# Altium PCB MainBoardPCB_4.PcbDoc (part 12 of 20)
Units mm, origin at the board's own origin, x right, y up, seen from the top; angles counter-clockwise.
Board outline 333.63 x 349.38 mm, 16 copper layers (L1, L2 (GND), L3 (Sign), L4 (GND), L5 (Sign), L6 (PWR/GND), L7(PWR/GND), L8 (Plane_GND), L9 (PWR/GND), L10 (PWR/GND), L11 (PWR/GND), L12 (Sign), L13 (GND), L14 (Sign), L15 (GND), L16), stack 2.502 mm thick; 2205 components, 1648 nets, 8314 pads, 3172 vias.
Unrouted connection lines stored in the file: 5141.
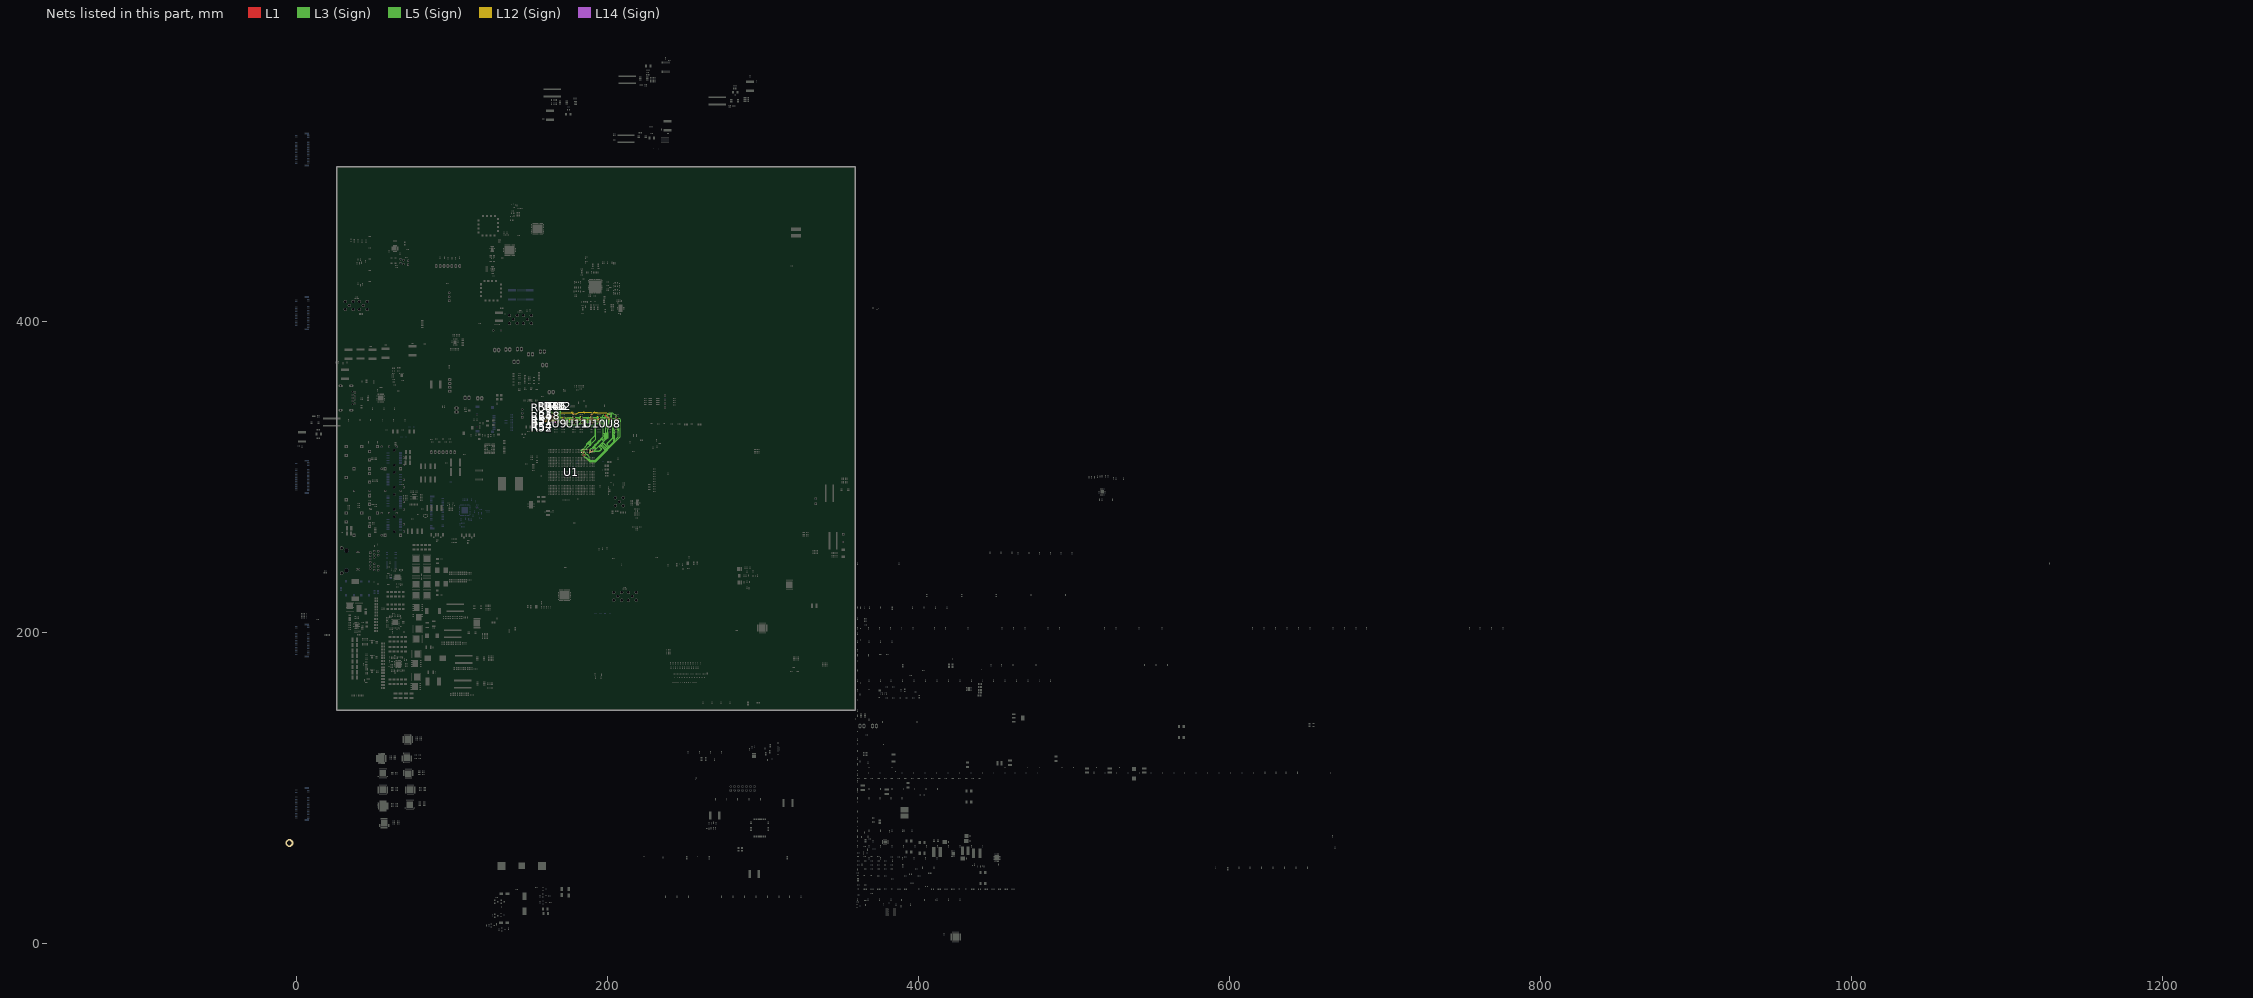
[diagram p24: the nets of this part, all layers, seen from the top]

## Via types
v1: diameter 0.5, hole 0.2, L1 to L16, tented both sides, 1153 vias
v2: diameter 0.5/0.35/0.35/0.35/0.35/0.35/0.35/0.35/0.35/0.35/0.35/0.35/0.35/0.35/0.35/0.5 (per signal layer), hole 0.2, L1 to L16, tented both sides, 548 vias
v3: diameter 0.5, hole 0.2, L1 to L16, 522 vias
v4: diameter 0.5/0.35/0.35/0.35/0.35/0.35/0.35/0.35/0.35/0.35/0.35/0.35/0.35/0.35/0.35/0.5 (per signal layer), hole 0.15, L1 to L16, tented both sides, 266 vias
v5: diameter 0.8, hole 0.4, L1 to L16, tented both sides, 164 vias
v6: diameter 0.35/0/0.35 (per signal layer), hole 0.127, L1 to L3 (Sign), tented both sides, 132 vias
v7: diameter 2.54, hole 1.02, L1 to L16, 125 vias
v8: diameter 1.4, hole 0.5, L1 to L16, tented both sides, 80 vias
v9: diameter 0.35, hole 0.127, L1 to L2 (GND), tented both sides, 36 vias
v10: diameter 0.4, hole 0.2, L1 to L16, 16 vias
v11: diameter 0.25, hole 0.2, L1 to L16, 16 vias
v12: diameter 5, hole 3, L1 to L16, 15 vias
v13: diameter 0.3, hole 0.2, L1 to L16, 15 vias
v14: diameter 0.45, hole 0.15, L1 to L16, 12 vias
v15: diameter 0.5/0.35/0.35/0.35/0.35/0.35/0.35/0.35/0.35/0.35/0.35/0.35/0.35/0.35/0.35/0.45 (per signal layer), hole 0.15, L1 to L16, tented both sides, 10 vias
v16: diameter 0.2/0/0.2 (per signal layer), hole 0.1, L1 to L3 (Sign), tented both sides, 9 vias
v17: diameter 0.4, hole 0.1, L1 to L16, 7 vias
v18: diameter 0.5, hole 0.2, L3 (Sign) to L6 (PWR/GND), tented both sides, 6 vias
v19: diameter 1.65, hole 1.65, L1 to L16, 6 vias
v20: diameter 1.15, hole 1.15, L1 to L16, 6 vias
v21: diameter 0.35/0/0.35 (per signal layer), hole 0.127, L14 (Sign) to L16, tented both sides, 5 vias
v22: diameter 0.2, hole 0.1, L1 to L16, 4 vias
v23: diameter 0.4, hole 0.2, L1 to L16, tented both sides, 2 vias
v24: diameter 0.4, hole 0.15, L1 to L16, 2 vias
v25: diameter 0.508, hole 0.127, L1 to L2 (GND), 2 vias
v26: diameter 0.508, hole 0.127, L2 (GND) to L3 (Sign), 2 vias
v27: diameter 0.5/0.35/0.35/0.35/0.35/0.35/0.35/0.35/0.35/0.35/0.35/0.35/0.35/0.35/0.35/0.5 (per signal layer), hole 0.15, L1 to L16, 2 vias
v28: diameter 0.35, hole 0.127, L3 (Sign) to L6 (PWR/GND), tented both sides, 2 vias
v29: diameter 5.5, hole 3.5, L1 to L16, 1 vias
v30: diameter 0.5/0.35/0.35/0.35/0.35/0.35/0.35/0.35/0.35/0.35/0.35/0.35/0.35/0.35/0.35/0.5 (per signal layer), hole 0.2, L1 to L16, 1 vias
v31: diameter 0.35/0.35/0.35 (per signal layer), hole 0.127, L1 to L3 (Sign), tented both sides, 1 vias
v32: diameter 0.45/0/0.45 (per signal layer), hole 0.15, L1 to L3 (Sign), tented both sides, 1 vias
v33: diameter 0.45/0/0.45 (per signal layer), hole 0.2, L14 (Sign) to L16, tented both sides, 1 vias
v34: diameter 0.35, hole 0.127, L2 (GND) to L3 (Sign), 1 vias
v35: diameter 0.35, hole 0.127, L1 to L2 (GND), 1 vias

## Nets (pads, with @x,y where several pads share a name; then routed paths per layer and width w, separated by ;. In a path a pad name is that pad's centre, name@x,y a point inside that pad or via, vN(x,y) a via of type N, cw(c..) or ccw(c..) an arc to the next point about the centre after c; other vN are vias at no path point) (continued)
DDR4_A12: R51.1 U1.AH29 U8.M4 U9.M4 U10.M4 U11.M4 | length 100.2
  L1 w0.116: U9.M4@167.676,336.86 168.072,337.257 v4(168.075,337.257) ; U11.M4@179.136,336.86 179.533,337.257 v4(179.535,337.257) ; U1.AH29@189.397,316.539 v6(189.884,317.027) ; U10.M4@190.597,336.86 190.993,337.257 v4(190.995,337.257) ; U8.M4@202.057,336.86 202.453,337.257 v4(202.456,337.257) v4@202.41,337.303
  L1 w0.155: R51.1@158.737,335.789 v1(159.982,335.789)
  L12 (Sign) w0.092: 165.251,336.237 165.445,336.237 165.539,336.143 165.892,336.143 166.604,336.855 167.465,336.855 167.867,337.257 v4(168.075,337.257) 168.075,337.251 168.611,336.715 173.117,336.715 173.251,336.715 ccw(c173.251,336.805) 173.34,336.805 173.34,336.915 cw(c173.43,336.915) 173.43,337.004 173.699,337.004 cw(c173.699,336.915) 173.788,336.915 173.788,336.805 ccw(c173.878,336.805) 173.878,336.715 174.146,336.715 ccw(c174.146,336.805) 174.236,336.805 174.236,336.915 cw(c174.326,336.915) 174.326,337.004 174.594,337.004 cw(c174.594,336.915) 174.684,336.915 174.684,336.805 ccw(c174.773,336.805) 174.773,336.715 175.743,336.715 177.622,336.715 177.768,336.86 179.109,336.86 179.505,337.257 v4(179.535,337.257) 180.267,337.257 180.961,336.563 184.861,336.563 185.159,336.86 186.83,336.86 187.355,336.86 ccw(c187.355,336.93) 187.425,336.93 187.425,337.109 cw(c187.494,337.109) 187.494,337.178 187.702,337.178 cw(c187.702,337.109) 187.771,337.109 187.771,336.86 187.771,336.612 ccw(c187.84,336.612) 187.84,336.543 188.048,336.543 ccw(c188.048,336.612) 188.117,336.612 188.117,336.791 cw(c188.186,336.791) 188.186,336.86 188.29,336.86 190.391,336.86 190.788,337.257 v4(190.995,337.257) 191.254,337.257 191.915,336.596 192.109,336.596 ccw(c192.109,336.626) 192.139,336.626 cw(c192.228,336.626) 192.228,336.715 192.497,336.715 cw(c192.497,336.626) 192.587,336.626 192.587,336.596 192.587,336.388 ccw(c192.676,336.388) 192.676,336.299 192.945,336.299 ccw(c192.945,336.388) 193.034,336.388 193.034,336.596 193.034,336.617 cw(c193.124,336.617) 193.124,336.707 193.393,336.707 cw(c193.393,336.617) 193.482,336.617 193.482,336.596 193.482,336.388 ccw(c193.572,336.388) 193.572,336.299 193.841,336.299 ccw(c193.841,336.388) 193.93,336.388 193.93,336.506 cw(c194.02,336.506) 194.02,336.596 194.288,336.596 cw(c194.288,336.506) 194.378,336.506 194.378,336.388 ccw(c194.467,336.388) 194.467,336.299 194.736,336.299 ccw(c194.736,336.388) 194.826,336.388 194.826,336.506 cw(c194.915,336.506) 194.915,336.596 195.123,336.596 201.075,336.596 201.394,336.915 201.768,336.915 202.155,337.303 202.41,337.303 v4(202.456,337.257)
  L12 (Sign) w0.151: v1(159.982,335.789) 163,335.789 163.448,336.237 165.251,336.237
  L3 (Sign) w0.092: v6(189.884,317.027) 190.205,316.706 191.727,316.706 199.386,324.364 199.765,324.364 200.51,325.11 200.51,328.276 200.406,328.38 200.406,330.432 200.406,331.001 cw(c200.505,331.001) 200.505,331.1 200.776,331.1 ccw(c200.776,331.199) 200.875,331.199 200.875,331.398 ccw(c200.776,331.398) 200.776,331.497 200.406,331.497 199.28,331.497 cw(c199.28,331.596) 199.181,331.596 199.181,331.795 cw(c199.28,331.795) 199.28,331.894 200.406,331.894 200.851,331.894 ccw(c200.851,331.993) 200.95,331.993 200.95,332.192 ccw(c200.851,332.192) 200.851,332.291 200.406,332.291 199.23,332.291 cw(c199.23,332.39) 199.13,332.39 199.13,332.589 cw(c199.23,332.589) 199.23,332.688 200.406,332.688 200.773,332.688 ccw(c200.773,332.787) 200.872,332.787 200.872,332.986 ccw(c200.773,332.986) 200.773,333.085 200.406,333.085 198.963,333.085 cw(c198.963,333.184) 198.864,333.184 198.864,333.383 cw(c198.963,333.383) 198.963,333.482 200.406,333.482 200.437,333.482 ccw(c200.437,333.581) 200.536,333.581 200.536,333.78 ccw(c200.437,333.78) 200.437,333.879 200.406,333.879 199.227,333.879 cw(c199.227,333.978) 199.128,333.978 199.128,334.177 cw(c199.227,334.177) 199.227,334.276 200.406,334.276 200.459,334.276 ccw(c200.459,334.375) 200.558,334.375 200.558,334.574 ccw(c200.459,334.574) 200.459,334.673 200.406,334.673 199.434,334.673 cw(c199.434,334.772) 199.334,334.772 199.334,334.971 cw(c199.434,334.971) 199.434,335.07 200.406,335.07 200.927,335.07 ccw(c200.927,335.169) 201.026,335.169 201.026,335.368 ccw(c200.927,335.368) 200.927,335.467 200.406,335.467 199.685,335.467 cw(c199.685,335.566) 199.586,335.566 199.586,335.765 cw(c199.685,335.765) 199.685,335.864 200.406,335.864 201.051,335.864 ccw(c201.051,335.963) 201.15,335.963 201.15,336.162 ccw(c201.051,336.162) 201.051,336.261 200.505,336.261 cw(c200.505,336.36) 200.406,336.36 200.406,336.459 200.807,336.86 202.059,336.86 v4(202.456,337.257)
DDR4_A13: R53.1 U1.AH28 U8.T5 U9.T5 U10.T5 U11.T5 | length 100.7
  L1 w0.116: U9.T5@166.876,340.06 167.274,340.459 v27(167.274,340.589) ; U11.T5@178.336,340.06 178.733,340.457 v4(178.735,340.457) ; v6(189.04,315.049) 189.04,315.182 U1.AH28@189.397,315.539 ; U10.T5@189.797,340.06 190.195,340.459 v4(190.195,340.589) ; U8.T5@201.257,340.06 201.653,340.457 v4(201.656,340.457)
  L1 w0.155: R53.1@158.737,344.5 v1(159.982,344.5)
  L12 (Sign) w0.092: 165.251,340.851 166.416,340.851 166.678,340.589 v27(167.274,340.589) 167.571,340.589 168.155,341.173 176.774,341.173 176.81,341.173 ccw(c176.81,341.262) 176.9,341.262 176.9,341.299 cw(c176.989,341.299) 176.989,341.389 177.258,341.389 cw(c177.258,341.299) 177.347,341.299 177.347,341.173 177.347,341.046 ccw(c177.437,341.046) 177.437,340.957 177.706,340.957 ccw(c177.706,341.046) 177.795,341.046 177.795,341.083 cw(c177.885,341.083) 177.885,341.173 178.019,341.173 v4(178.735,340.457) 180.475,340.457 181.559,341.541 184.15,341.541 184.793,341.541 ccw(c184.793,341.61) 184.862,341.61 184.862,341.755 cw(c184.931,341.755) 184.931,341.824 185.139,341.824 cw(c185.139,341.755) 185.208,341.755 185.208,341.541 185.208,341.327 ccw(c185.277,341.327) 185.277,341.258 185.485,341.258 ccw(c185.485,341.327) 185.554,341.327 185.554,341.472 cw(c185.624,341.472) 185.624,341.541 185.727,341.541 189.243,341.541 v4(190.195,340.589) 190.492,340.589 191.076,341.173 191.211,341.173 ccw(c191.211,341.262) 191.3,341.262 191.3,341.434 cw(c191.39,341.434) 191.39,341.523 191.658,341.523 cw(c191.658,341.434) 191.748,341.434 191.748,341.262 ccw(c191.838,341.262) 191.838,341.173 192.106,341.173 ccw(c192.106,341.262) 192.196,341.262 192.196,341.434 cw(c192.285,341.434) 192.285,341.523 192.554,341.523 cw(c192.554,341.434) 192.644,341.434 192.644,341.262 ccw(c192.733,341.262) 192.733,341.173 193.002,341.173 ccw(c193.002,341.262) 193.091,341.262 193.091,341.434 cw(c193.181,341.434) 193.181,341.523 193.45,341.523 cw(c193.45,341.434) 193.539,341.434 193.539,341.262 ccw(c193.629,341.262) 193.629,341.173 194.164,341.173 199.436,341.173 200.152,340.457 v4(201.656,340.457)
  L12 (Sign) w0.151: v1(159.982,344.5) 160.782,344.5 164.431,340.851 165.251,340.851
  L3 (Sign) w0.092: v6(189.04,315.049) 189.04,315.182 189.546,315.688 189.546,316.37 189.04,316.876 189.04,317.636 189.793,318.389 190.017,318.389 190.158,318.529 cw(c190.199,318.571) 190.158,318.612 190.355,318.81 cw(c190.397,318.769) 190.438,318.81 190.855,318.394 ccw(c190.925,318.464) 190.995,318.394 191.136,318.534 ccw(c191.065,318.604) 191.136,318.674 190.719,319.091 cw(c190.761,319.132) 190.719,319.174 190.917,319.372 cw(c190.958,319.33) 191,319.372 192.149,318.222 ccw(c192.22,318.292) 192.29,318.222 192.43,318.362 ccw(c192.36,318.433) 192.43,318.503 191.281,319.652 cw(c191.322,319.694) 191.281,319.735 191.478,319.933 cw(c191.52,319.891) 191.561,319.933 191.795,319.699 ccw(c191.866,319.769) 191.936,319.699 192.076,319.839 ccw(c192.006,319.909) 192.076,319.98 191.842,320.214 cw(c191.884,320.255) 191.842,320.297 192.04,320.494 cw(c192.081,320.453) 192.123,320.494 192.357,320.26 ccw(c192.427,320.33) 192.497,320.26 192.638,320.401 ccw(c192.567,320.471) 192.638,320.541 192.404,320.775 cw(c192.445,320.817) 192.404,320.858 192.601,321.056 cw(c192.643,321.014) 192.684,321.056 192.918,320.822 ccw(c192.989,320.892) 193.059,320.822 193.199,320.962 ccw(c193.129,321.032) 193.199,321.102 192.965,321.337 cw(c193.007,321.378) 192.965,321.42 193.163,321.617 cw(c193.204,321.576) 193.246,321.617 193.48,321.383 ccw(c193.55,321.453) 193.62,321.383 193.761,321.524 ccw(c193.69,321.594) 193.761,321.664 193.526,321.898 cw(c193.568,321.94) 193.526,321.981 193.724,322.179 cw(c193.766,322.137) 193.807,322.179 194.041,321.945 ccw(c194.111,322.015) 194.182,321.945 194.322,322.085 ccw(c194.252,322.155) 194.322,322.225 194.088,322.459 cw(c194.129,322.501) 194.088,322.543 194.285,322.74 cw(c194.327,322.699) 194.369,322.74 194.603,322.506 ccw(c194.673,322.576) 194.743,322.506 194.883,322.646 ccw(c194.813,322.717) 194.883,322.787 194.649,323.021 cw(c194.691,323.062) 194.649,323.104 194.847,323.302 cw(c194.888,323.26) 194.93,323.302 195.164,323.068 ccw(c195.234,323.138) 195.304,323.068 195.445,323.208 ccw(c195.375,323.278) 195.445,323.348 195.211,323.582 cw(c195.252,323.624) 195.211,323.665 195.408,323.863 cw(c195.45,323.821) 195.491,323.863 195.726,323.629 ccw(c195.796,323.699) 195.866,323.629 196.006,323.769 ccw(c195.936,323.84) 196.006,323.91 195.772,324.144 cw(c195.814,324.185) 195.772,324.227 195.97,324.424 cw(c196.011,324.383) 196.053,324.425 197.051,323.427 ccw(c197.121,323.497) 197.191,323.427 197.331,323.567 ccw(c197.261,323.637) 197.331,323.708 196.334,324.705 196.211,324.828 cw(c196.281,324.898) 196.211,324.968 196.351,325.109 cw(c196.421,325.039) 196.492,325.109 196.544,325.056 ccw(c196.614,325.126) 196.685,325.056 196.759,325.131 197.28,325.652 197.28,334.491 201.168,338.379 201.975,338.379 202.135,338.538 202.135,338.99 202.323,339.178 ; v4(201.656,340.457) 202.379,340.457 202.616,340.22 202.616,339.47 202.323,339.178
DDR4_ACT_N: R40.1 U1.AD26 U8.L3 U9.L3 U10.L3 U11.L3 | length 104
  L1 w0.116: v4(170.472,335.657) U9.L3@170.876,336.06 ; v4(181.933,335.657) U11.L3@182.336,336.06 ; U1.AD26@185.397,313.539 185.89,314.033 v6(186.017,314.033) ; v4(193.393,335.657) U10.L3@193.797,336.06 ; U8.L3@205.257,336.06 v15(205.661,335.657)
  L1 w0.155: v1(166.395,343.555) R40.1@166.395,344.799
  L5 (Sign) w0.092: 168.694,341.085 168.694,340.953 168.985,340.662 168.985,337.144 v4(170.472,335.657) 170.824,336.008 173.503,336.008 174.251,335.26 175.057,335.26 175.191,335.26 ccw(c175.191,335.35) 175.281,335.35 175.281,335.407 cw(c175.37,335.407) 175.37,335.497 175.639,335.497 cw(c175.639,335.407) 175.728,335.407 175.728,335.26 175.728,335.13 ccw(c175.818,335.13) 175.818,335.04 176.087,335.04 ccw(c176.087,335.13) 176.176,335.13 176.176,335.171 cw(c176.266,335.171) 176.266,335.26 176.657,335.26 180.028,335.26 180.425,335.657 v4(181.933,335.657) 182.336,336.06 184.472,336.06 185.265,335.267 185.356,335.267 185.46,335.267 ccw(c185.46,335.337) 185.53,335.337 185.53,335.406 cw(c185.599,335.406) 185.599,335.475 185.807,335.475 cw(c185.807,335.406) 185.876,335.406 185.876,335.267 185.876,335.129 ccw(c185.945,335.129) 185.945,335.059 186.153,335.059 ccw(c186.153,335.129) 186.222,335.129 186.222,335.267 186.222,335.406 cw(c186.291,335.406) 186.291,335.475 186.499,335.475 cw(c186.499,335.406) 186.568,335.406 186.568,335.337 ccw(c186.637,335.337) 186.637,335.267 186.715,335.267 191.656,335.267 192.045,335.657 v4(193.393,335.657) 193.816,336.08 195.631,336.08 195.885,335.826 197.417,335.826 198.076,335.826 cw(c198.076,335.737) 198.165,335.737 198.165,335.628 ccw(c198.255,335.628) 198.255,335.539 198.523,335.539 ccw(c198.523,335.628) 198.613,335.628 198.613,335.826 198.613,335.844 cw(c198.702,335.844) 198.702,335.933 198.971,335.933 cw(c198.971,335.844) 199.061,335.844 199.061,335.826 199.061,335.628 ccw(c199.15,335.628) 199.15,335.539 199.419,335.539 ccw(c199.419,335.628) 199.509,335.628 199.509,335.826 199.509,335.844 cw(c199.598,335.844) 199.598,335.933 199.867,335.933 cw(c199.867,335.844) 199.956,335.844 199.956,335.826 199.956,335.628 ccw(c200.046,335.628) 200.046,335.539 200.315,335.539 ccw(c200.315,335.628) 200.404,335.628 200.404,335.826 200.404,336.024 cw(c200.494,336.024) 200.494,336.113 200.762,336.113 cw(c200.762,336.024) 200.852,336.024 200.852,335.916 ccw(c200.941,335.916) 200.941,335.826 201.3,335.826 201.524,335.826 202.667,335.826 202.971,336.131 204.711,336.131 205.41,336.829 205.765,336.829 205.974,336.62 205.974,335.978 205.661,335.664 v15(205.661,335.657)
  L5 (Sign) w0.151: v1(166.395,343.555) 167.071,342.879 167.648,342.879 168.694,341.833 168.694,341.085
  L3 (Sign) w0.092: v6(186.017,314.033) 186.498,314.514 187.085,314.514 187.528,314.071 187.528,313.862 188.205,313.185 188.205,313.181 188.227,313.16 188.227,311.353 188.962,310.618 192.216,310.618 204.202,322.604 204.202,322.802 204.202,323.1 cw(c204.301,323.1) 204.301,323.199 204.674,323.199 ccw(c204.674,323.299) 204.774,323.299 204.774,323.497 ccw(c204.674,323.497) 204.674,323.596 204.301,323.596 cw(c204.301,323.696) 204.202,323.696 204.202,323.894 cw(c204.301,323.894) 204.301,323.993 204.674,323.993 ccw(c204.674,324.093) 204.774,324.093 204.774,324.291 ccw(c204.674,324.291) 204.674,324.39 204.301,324.39 cw(c204.301,324.49) 204.202,324.49 204.202,324.688 cw(c204.301,324.688) 204.301,324.787 204.6,324.787 ccw(c204.6,324.887) 204.699,324.887 204.699,325.085 ccw(c204.6,325.085) 204.6,325.184 204.301,325.184 cw(c204.301,325.284) 204.202,325.284 204.202,325.482 cw(c204.301,325.482) 204.301,325.581 204.6,325.581 ccw(c204.6,325.681) 204.699,325.681 204.699,325.879 ccw(c204.6,325.879) 204.6,325.978 204.301,325.978 cw(c204.301,326.078) 204.202,326.078 204.202,326.276 cw(c204.301,326.276) 204.301,326.375 204.674,326.375 ; 204.674,326.375 ccw(c204.674,326.475) 204.774,326.475 204.774,326.673 ccw(c204.674,326.673) 204.674,326.772 204.301,326.772 cw(c204.301,326.872) 204.202,326.872 204.202,327.07 cw(c204.301,327.07) 204.301,327.169 204.386,327.169 ccw(c204.386,327.269) 204.486,327.269 204.486,327.467 ccw(c204.386,327.467) 204.386,327.566 204.301,327.566 cw(c204.301,327.666) 204.202,327.666 204.202,327.864 cw(c204.301,327.864) 204.301,327.963 204.579,327.963 ccw(c204.579,328.063) 204.678,328.063 204.678,328.261 ccw(c204.579,328.261) 204.579,328.36 204.301,328.36 cw(c204.301,328.46) 204.202,328.46 204.202,328.658 cw(c204.301,328.658) 204.301,328.757 204.392,328.757 ccw(c204.392,328.857) 204.491,328.857 204.491,329.055 ccw(c204.392,329.055) 204.392,329.154 204.301,329.154 cw(c204.301,329.254) 204.202,329.254 204.202,329.452 cw(c204.301,329.452) 204.301,329.551 204.56,329.551 ccw(c204.56,329.651) 204.659,329.651 204.659,329.849 ccw(c204.56,329.849) 204.56,329.948 204.301,329.948 cw(c204.301,330.048) 204.202,330.048 204.202,332.168 204.202,334.623 204.349,334.771 204.349,335.21 204.584,335.445 205.207,335.445 205.418,335.657 v15(205.661,335.657)
DDR4_ALERT_N: R58.1 U1.AB24 U8.P6 U9.P6 U10.P6 U11.P6 | length 42.4
  L1 w0.112: 165.251,338.856 v6(165.665,338.856) ; U9.P6@166.061,338.46 U9.P6@166.076,338.46
  L1 w0.116: v6(165.665,338.856) U9.P6@166.061,338.46 ; v6@177.125,338.856 U11.P6@177.529,338.453 ; v6(188.586,338.856) U10.P6@188.989,338.453 ; v6(198.298,339.928) 199.766,338.46 U8.P6@200.457,338.46
  L1 w0.155: R58.1@163.36,339.242 164.63,339.242 165.016,338.856 165.251,338.856
  L3 (Sign) w0.092: v6(165.665,338.856) 166.061,338.46 168.322,338.46 169.953,336.829 174.409,336.829 176.04,338.46 176.721,338.46
  L3 (Sign) w0.116: 176.721,338.46 v6(177.117,338.857) 177.514,338.46 188.189,338.46 v6(188.586,338.856) 188.982,338.46 196.259,338.46 197.727,339.928 v6(198.298,339.928)
DDR4_BA0: R32.1 U1.AD27 U8.N2 U9.N2 U10.N2 U11.N2 | length 102.4
  L1 w0.116: U9.N2@171.676,337.66 v4(172.079,338.064) ; U11.N2@183.136,337.66 v4(183.54,338.064) ; v6(184.912,313.919) 184.912,314.054 U1.AD27@185.397,314.539 ; U10.N2@194.597,337.66 v4(195,338.064) ; U8.N2@206.057,337.66 v15(206.439,338.042)
  L1 w0.155: v1(170.02,343.555) R32.1@170.02,344.799
  L5 (Sign) w0.092: 169.765,341.085 169.569,340.89 169.569,338.367 170.243,337.693 170.626,337.693 170.996,337.693 171.367,338.064 v4(172.079,338.064) 173.24,338.064 173.687,337.617 173.876,337.617 174.01,337.617 ccw(c174.01,337.706) 174.1,337.706 174.1,337.818 cw(c174.189,337.818) 174.189,337.907 174.458,337.907 cw(c174.458,337.818) 174.547,337.818 174.547,337.617 174.547,337.416 ccw(c174.637,337.416) 174.637,337.326 174.906,337.326 ccw(c174.906,337.416) 174.995,337.416 174.995,337.527 cw(c175.085,337.527) 175.085,337.617 175.927,337.617 182.674,337.617 183.122,338.064 v4(183.54,338.064) 183.822,338.064 183.909,337.977 183.909,337.857 184.098,337.668 186.347,337.668 186.968,337.668 ccw(c186.968,337.737) 187.037,337.737 187.037,337.823 cw(c187.106,337.823) 187.106,337.892 187.314,337.892 cw(c187.314,337.823) 187.383,337.823 187.383,337.668 187.383,337.512 ccw(c187.453,337.512) 187.453,337.443 187.66,337.443 ccw(c187.66,337.512) 187.73,337.512 187.73,337.668 187.73,337.823 cw(c187.799,337.823) 187.799,337.892 188.006,337.892 cw(c188.006,337.823) 188.076,337.823 188.076,337.668 188.076,337.633 ccw(c188.145,337.633) 188.145,337.563 188.353,337.563 ccw(c188.353,337.633) 188.422,337.633 cw(c188.457,337.633) 188.457,337.668 188.595,337.668 194.056,337.668 194.452,338.064 v4(195,338.064) 195.313,338.064 195.952,338.064 cw(c195.952,337.974) 196.041,337.974 196.041,337.85 ccw(c196.131,337.85) 196.131,337.761 196.399,337.761 ccw(c196.399,337.85) 196.489,337.85 196.489,337.974 cw(c196.578,337.974) 196.578,338.064 196.847,338.064 cw(c196.847,337.974) 196.937,337.974 196.937,337.85 ccw(c197.026,337.85) 197.026,337.761 197.295,337.761 ccw(c197.295,337.85) 197.384,337.85 197.384,338.064 197.384,338.223 cw(c197.474,338.223) 197.474,338.312 197.743,338.312 cw(c197.743,338.223) 197.832,338.223 197.832,338.064 197.832,337.85 ccw(c197.922,337.85) 197.922,337.761 198.191,337.761 ccw(c198.191,337.85) 198.28,337.85 198.28,338.064 198.28,338.223 cw(c198.37,338.223) 198.37,338.312 198.638,338.312 cw(c198.638,338.223) 198.728,338.223 198.728,338.064 198.728,337.85 ccw(c198.817,337.85) 198.817,337.761 199.086,337.761 ccw(c199.086,337.85) 199.176,337.85 199.176,338.064 199.176,338.223 cw(c199.265,338.223) 199.265,338.312 199.534,338.312 cw(c199.534,338.223) 199.623,338.223 199.623,338.064 199.623,337.85 ccw(c199.713,337.85) 199.713,337.761 199.982,337.761 ccw(c199.982,337.85) 200.071,337.85 200.071,338.064 200.071,338.223 cw(c200.161,338.223) 200.161,338.312 200.43,338.312 cw(c200.43,338.223) 200.519,338.223 200.519,338.064 200.519,337.85 ccw(c200.609,337.85) 200.609,337.761 200.877,337.761 ccw(c200.877,337.85) 200.967,337.85 200.967,337.974 cw(c201.056,337.974) 201.056,338.064 201.191,338.064 201.587,337.668 201.752,337.668 ccw(c201.752,337.727) 201.811,337.727 cw(c201.9,337.727) 201.9,337.817 202.169,337.817 cw(c202.169,337.727) 202.258,337.727 ccw(c202.318,337.727) 202.318,337.668 202.654,337.668 205.646,337.668 206.02,338.042 v15(206.439,338.042)
  L5 (Sign) w0.151: 169.765,341.085 170.02,341.341 v1(170.02,343.555)
  L3 (Sign) w0.092: v6(184.912,313.919) 184.912,313.655 185.312,313.255 185.312,312.828 185.749,312.391 185.756,312.398 186.088,312.398 188.679,309.807 192.491,309.807 192.53,309.846 192.538,309.846 208.407,325.715 208.407,334.442 208.407,335.21 ccw(c208.32,335.21) 208.32,335.297 208.095,335.297 cw(c208.095,335.383) 208.008,335.383 208.008,335.557 cw(c208.095,335.557) 208.095,335.643 208.407,335.643 ccw(c208.407,335.708) 208.472,335.708 208.472,335.925 ccw(c208.407,335.925) 208.407,335.989 208.095,335.989 cw(c208.095,336.076) 208.008,336.076 208.008,336.249 cw(c208.095,336.249) 208.095,336.336 208.32,336.336 ccw(c208.32,336.422) 208.407,336.422 208.407,336.682 208.407,336.855 207.582,337.68 206.8,337.68 v15(206.439,338.042)
DDR4_BA1: R34.1 U1.AC26 U8.N5 U9.N5 U10.N5 U11.N5 | length 99
  L1 w0.116: U9.N5@166.876,337.66 167.272,338.057 v27(167.275,338.057) ; U11.N5@178.336,337.66 178.733,338.057 v4(178.735,338.057) ; v6(183.91,314.027) U1.AC26@184.397,313.539 ; U10.N5@189.797,337.66 190.193,338.057 v4(190.195,338.057) ; U8.N5@201.257,337.66 201.653,338.057 v4(201.656,338.057)
  L1 w0.155: R34.1@158.737,339.055 v1(159.982,339.056)
  L12 (Sign) w0.092: 165.251,338.057 166.745,338.057 v27(167.275,338.057) 167.511,338.057 167.915,338.46 168.465,338.46 168.6,338.46 ccw(c168.6,338.55) 168.689,338.55 168.689,338.564 cw(c168.779,338.564) 168.779,338.654 169.048,338.654 cw(c169.048,338.564) 169.137,338.564 169.137,338.46 169.137,338.144 ccw(c169.227,338.144) 169.227,338.054 169.495,338.054 ccw(c169.495,338.144) 169.585,338.144 169.585,338.371 cw(c169.675,338.371) 169.675,338.46 170.345,338.46 172.412,338.46 172.816,338.057 v4(178.735,338.057) 178.981,338.303 179.327,338.303 179.402,338.378 179.413,338.378 179.515,338.48 181.75,338.48 182.479,338.48 ccw(c182.479,338.55) 182.548,338.55 182.548,338.785 cw(c182.617,338.785) 182.617,338.854 182.825,338.854 cw(c182.825,338.785) 182.894,338.785 182.894,338.48 182.894,338.176 ccw(c182.963,338.176) 182.963,338.107 183.171,338.107 ccw(c183.171,338.176) 183.24,338.176 183.24,338.411 cw(c183.31,338.411) 183.31,338.48 183.413,338.48 189.243,338.48 189.666,338.057 v4(190.195,338.057) 190.458,338.057 190.805,338.404 191.783,338.404 193.558,338.404 ccw(c193.558,338.494) 193.648,338.494 193.648,338.57 cw(c193.737,338.57) 193.737,338.659 194.006,338.659 cw(c194.006,338.57) 194.096,338.57 194.096,338.404 194.096,338.145 ccw(c194.185,338.145) 194.185,338.055 194.454,338.055 ccw(c194.454,338.145) 194.543,338.145 194.543,338.315 cw(c194.633,338.315) 194.633,338.404 194.767,338.404 195.389,338.404 195.986,337.807 198.869,337.807 199.09,337.807 ccw(c199.09,337.87) 199.153,337.87 cw(c199.242,337.87) 199.242,337.96 199.511,337.96 cw(c199.511,337.87) 199.601,337.87 199.601,337.807 199.601,337.744 ccw(c199.69,337.744) 199.69,337.655 199.959,337.655 ccw(c199.959,337.744) 200.049,337.744 200.049,337.807 200.049,337.87 cw(c200.138,337.87) 200.138,337.96 200.407,337.96 cw(c200.407,337.87) 200.496,337.87 200.496,337.807 200.496,337.744 ccw(c200.586,337.744) 200.586,337.655 200.855,337.655 ccw(c200.855,337.744) 200.944,337.744 cw(c201.007,337.744) 201.007,337.807 201.168,337.807 201.418,338.057 v4(201.656,338.057)
  L12 (Sign) w0.151: v1(159.982,339.056) 160.336,338.702 161.577,338.702 162.221,338.057 165.251,338.057
  L3 (Sign) w0.092: v6(183.91,314.027) 183.91,314.68 184.362,315.132 184.362,316.073 183.563,316.872 183.563,317.185 183.751,317.373 183.934,317.373 184.164,317.603 184.62,317.603 184.723,317.707 185.751,317.707 ; 185.751,317.706 186.114,317.706 186.535,318.126 188.044,319.659 188.084,319.7 188.536,320.159 188.606,320.23 ccw(c188.535,320.299) 188.605,320.37 188.073,320.894 cw(c188.143,320.964) 188.072,321.034 188.211,321.175 cw(c188.282,321.106) 188.352,321.176 188.954,320.583 189.115,320.425 ccw(c189.185,320.496) 189.255,320.426 189.395,320.567 ccw(c189.324,320.637) 189.393,320.708 189.232,320.866 188.634,321.455 cw(c188.704,321.526) 188.633,321.595 188.773,321.737 cw(c188.843,321.667) 188.913,321.738 189.44,321.219 ccw(c189.51,321.29) 189.581,321.22 189.72,321.361 ccw(c189.649,321.431) 189.719,321.502 189.196,322.017 cw(c189.266,322.087) 189.195,322.157 189.334,322.298 cw(c189.405,322.229) 189.474,322.299 189.997,321.785 ccw(c190.067,321.855) 190.138,321.786 190.346,321.998 190.907,322.567 192.661,324.322 192.661,333.733 193.022,334.093 193.022,334.211 193.239,334.428 193.264,334.428 193.264,334.453 193.633,334.453 194.441,335.26 195.71,335.26 201.227,340.778 202.345,340.778 202.857,340.266 202.857,338.633 202.667,338.442 202.383,338.442 201.998,338.057 v4(201.656,338.057)
DDR4_BG0: R36.1 U1.AC28 U8.M2 U9.M2 U10.M2 U11.M2 | length 104.5
  L1 w0.116: U9.M2@171.676,336.86 v4(172.079,337.264) ; U11.M2@183.136,336.86 v4(183.54,337.264) ; v6(183.909,316.027) U1.AC28@184.397,315.539 ; U10.M2@194.597,336.86 v4(195,337.264) ; v15(205.684,337.233) U8.M2@206.057,336.86 U8.M2@206.088,336.829
  L1 w0.155: v1(167.603,343.555) R36.1@167.603,344.8
  L5 (Sign) w0.092: 169.102,341.085 169.102,340.891 169.177,340.816 169.177,337.543 170.231,336.488 171.303,336.488 v4(172.079,337.264) 172.324,337.264 173.043,336.545 173.609,336.545 173.708,336.545 cw(c173.708,336.445) 173.807,336.445 173.807,336.406 ccw(c173.907,336.406) 173.907,336.307 174.105,336.307 ccw(c174.105,336.406) 174.204,336.406 174.204,336.445 cw(c174.304,336.445) 174.304,336.545 175.12,336.545 177.437,336.545 177.921,336.06 181.217,336.06 181.292,336.136 181.922,336.766 183.042,336.766 v4(183.54,337.264) 183.54,336.919 183.998,336.461 184.595,336.461 184.996,336.06 186.741,336.06 187.533,336.06 ccw(c187.533,336.13) 187.603,336.13 187.603,336.176 cw(c187.672,336.176) 187.672,336.245 187.879,336.245 cw(c187.879,336.176) 187.949,336.176 187.949,336.06 187.949,335.991 ccw(c188.018,335.991) 188.018,335.922 188.226,335.922 ccw(c188.226,335.991) 188.295,335.991 cw(c188.364,335.991) 188.364,336.06 188.468,336.06 192.677,336.06 193.383,336.766 194.502,336.766 v4(195,337.264) 195.79,336.474 195.925,336.474 ccw(c195.925,336.563) 196.014,336.563 196.014,336.726 cw(c196.104,336.726) 196.104,336.816 196.373,336.816 cw(c196.373,336.726) 196.462,336.726 196.462,336.474 196.462,336.221 ccw(c196.552,336.221) 196.552,336.131 196.82,336.131 ccw(c196.82,336.221) 196.91,336.221 196.91,336.474 196.91,336.65 cw(c197,336.65) 197,336.739 197.268,336.739 cw(c197.268,336.65) 197.358,336.65 197.358,336.474 197.358,336.221 ccw(c197.447,336.221) 197.447,336.131 197.716,336.131 ccw(c197.716,336.221) 197.806,336.221 197.806,336.474 197.806,336.65 cw(c197.895,336.65) 197.895,336.739 198.164,336.739 cw(c198.164,336.65) 198.253,336.65 198.253,336.474 198.253,336.221 ccw(c198.343,336.221) 198.343,336.131 198.612,336.131 ccw(c198.612,336.221) 198.701,336.221 198.701,336.474 198.701,336.65 cw(c198.791,336.65) 198.791,336.739 199.059,336.739 cw(c199.059,336.65) 199.149,336.65 199.149,336.474 199.149,336.221 ccw(c199.239,336.221) 199.239,336.131 199.507,336.131 ccw(c199.507,336.221) 199.597,336.221 199.597,336.474 199.597,336.726 cw(c199.686,336.726) 199.686,336.816 199.955,336.816 cw(c199.955,336.726) 200.045,336.726 200.045,336.563 ccw(c200.134,336.563) 200.134,336.474 200.952,336.474 200.965,336.474 201.378,336.061 202.045,336.061 202.619,336.061 203.161,336.602 204.649,336.602 205.28,337.233 v15(205.684,337.233)
  L5 (Sign) w0.151: v1(167.603,343.555) 167.603,343.534 169.102,342.035 169.102,341.085
  L3 (Sign) w0.092: v6(183.909,316.027) 183.909,316.254 183.371,316.792 183.371,317.264 183.672,317.565 183.854,317.565 184.084,317.795 184.327,317.795 185.692,319.16 185.692,319.238 186.638,320.183 186.638,321.172 186.846,321.38 cw(c186.916,321.309) 186.986,321.38 187.332,321.033 ccw(c187.403,321.103) 187.473,321.033 187.613,321.173 ccw(c187.543,321.244) 187.613,321.314 187.267,321.66 cw(c187.337,321.731) 187.267,321.801 187.407,321.941 cw(c187.477,321.871) 187.547,321.941 187.894,321.595 ccw(c187.964,321.665) 188.034,321.595 188.175,321.735 ccw(c188.104,321.805) 188.175,321.875 187.828,322.222 cw(c187.898,322.292) 187.828,322.362 ; 187.828,322.362 187.968,322.503 cw(c188.039,322.432) 188.109,322.503 188.455,322.156 ccw(c188.526,322.226) 188.596,322.156 188.736,322.296 ccw(c188.666,322.367) 188.736,322.437 188.389,322.783 cw(c188.46,322.853) 188.389,322.924 188.53,323.064 cw(c188.6,322.994) 188.67,323.064 189.017,322.717 ccw(c189.087,322.788) 189.157,322.717 189.298,322.858 ccw(c189.227,322.928) 189.298,322.998 188.951,323.345 cw(c189.021,323.415) 188.951,323.485 189.091,323.625 cw(c189.161,323.555) 189.232,323.625 189.277,323.58 ccw(c189.347,323.651) 189.417,323.58 189.557,323.721 ccw(c189.487,323.791) 189.557,323.861 189.512,323.906 cw(c189.583,323.976) 189.512,324.047 189.583,324.117 192.129,326.663 192.129,333.743 192.638,334.252 192.638,334.484 192.862,334.708 192.862,335.892 193.266,336.296 196.202,336.296 201.206,341.3 203.073,341.3 203.733,340.639 204.224,340.639 204.72,340.143 204.903,340.143 205.58,339.466 205.58,337.579 205.621,337.538 205.621,337.296 v15(205.684,337.233)
DDR4_BG1: U1.AC27
DDR4_CAS: R57.1 U1.AJ29 U8.M5 U9.M5 U10.M5 U11.M5 | length 98.2
  L1 w0.116: U9.M5@166.876,336.86 167.272,337.257 v4(167.275,337.257) ; U11.M5@178.336,336.86 178.733,337.257 v4(178.735,337.257) ; U10.M5@189.797,336.86 190.193,337.257 v4(190.195,337.257) ; U1.AJ29@190.397,316.539 v6(190.884,317.027) ; U8.M5@201.257,336.86 201.259,336.86 v4(201.656,337.257)
  L1 w0.155: R57.1@158.737,336.878 v1(159.982,336.878)
  L12 (Sign) w0.092: 165.251,336.878 165.496,336.878 165.519,336.855 166.07,336.855 166.472,337.257 166.72,337.257 v4(167.275,337.257) 167.486,337.257 167.807,337.578 168.208,337.578 168.878,336.907 169.013,336.907 ccw(c169.013,336.997) 169.102,336.997 169.102,337.062 cw(c169.192,337.062) 169.192,337.152 169.46,337.152 cw(c169.46,337.062) 169.55,337.062 169.55,336.997 ccw(c169.64,336.997) 169.64,336.907 169.672,336.907 170.688,336.907 170.822,336.907 ccw(c170.822,336.997) 170.912,336.997 170.912,337.1 cw(c171.001,337.1) 171.001,337.189 171.27,337.189 cw(c171.27,337.1) 171.36,337.1 171.36,336.997 ccw(c171.449,336.997) 171.449,336.907 171.952,336.907 172.661,336.907 173.01,337.257 v4(178.735,337.257) 178.911,337.257 179.248,337.593 180.711,337.593 181.424,336.88 184.497,336.88 185.277,337.66 185.45,337.66 185.727,337.66 cw(c185.727,337.591) 185.797,337.591 185.797,337.419 ccw(c185.866,337.419) 185.866,337.35 186.074,337.35 ccw(c186.074,337.419) 186.143,337.419 186.143,337.66 186.143,337.741 cw(c186.212,337.741) 186.212,337.81 186.42,337.81 cw(c186.42,337.741) 186.489,337.741 186.489,337.73 ccw(c186.558,337.73) 186.558,337.66 186.665,337.66 189.237,337.66 189.641,337.257 v4(190.195,337.257) 190.407,337.257 190.728,337.578 190.862,337.578 191.128,337.578 191.275,337.578 191.946,336.907 193.52,336.907 193.654,336.907 ccw(c193.654,336.997) 193.744,336.997 193.744,337.087 cw(c193.833,337.087) 193.833,337.177 194.102,337.177 cw(c194.102,337.087) 194.192,337.087 194.192,336.907 ccw(c194.281,336.907) 194.281,336.818 194.55,336.818 ccw(c194.55,336.907) 194.639,336.907 194.639,336.877 cw(c194.669,336.877) 194.669,336.907 195,336.907 195.047,336.907 195.631,336.907 195.844,336.907 ccw(c195.844,336.997) 195.934,336.997 195.934,337.081 cw(c196.023,337.081) 196.023,337.171 196.292,337.171 cw(c196.292,337.081) 196.382,337.081 196.382,336.907 196.382,336.877 ccw(c196.471,336.877) 196.471,336.787 196.74,336.787 ccw(c196.74,336.877) 196.829,336.877 cw(c196.859,336.877) 196.859,336.907 197.053,336.907 197.432,336.907 197.85,336.907 cw(c197.85,336.877) 197.88,336.877 ccw(c197.969,336.877) 197.969,336.787 198.238,336.787 ccw(c198.238,336.877) 198.327,336.877 198.327,336.907 198.327,336.987 cw(c198.417,336.987) 198.417,337.077 198.686,337.077 cw(c198.686,336.987) 198.775,336.987 198.775,336.907 198.775,336.877 ccw(c198.865,336.877) 198.865,336.787 199.133,336.787 ccw(c199.133,336.877) 199.223,336.877 cw(c199.253,336.877) 199.253,336.907 199.641,336.907 cw(c199.641,336.877) 199.671,336.877 ccw(c199.76,336.877) 199.76,336.787 200.029,336.787 ccw(c200.029,336.877) 200.119,336.877 cw(c200.149,336.877) 200.149,336.907 200.343,336.907 200.979,336.907 201.329,337.257 v4(201.656,337.257)
  L12 (Sign) w0.151: v1(159.982,336.878) 165.251,336.878
  L3 (Sign) w0.092: v6(190.884,317.027) 191.737,317.027 191.8,317.09 198.886,324.176 198.984,324.273 198.984,324.372 ccw(c198.884,324.372) 198.884,324.471 198.047,324.471 cw(c198.047,324.571) 197.947,324.571 197.947,324.769 cw(c198.047,324.769) 198.047,324.868 198.984,324.868 199.775,324.868 ccw(c199.775,324.968) 199.874,324.968 199.874,325.166 ccw(c199.775,325.166) 199.775,325.265 198.984,325.265 198.047,325.265 cw(c198.047,325.365) 197.947,325.365 197.947,325.563 cw(c198.047,325.563) 198.047,325.662 198.984,325.662 200.037,325.662 ccw(c200.037,325.762) 200.136,325.762 200.136,325.96 ccw(c200.037,325.96) 200.037,326.059 198.984,326.059 198.047,326.059 cw(c198.047,326.159) 197.947,326.159 197.947,326.357 cw(c198.047,326.357) 198.047,326.456 198.984,326.456 200.037,326.456 ccw(c200.037,326.556) 200.136,326.556 200.136,326.754 ccw(c200.037,326.754) 200.037,326.853 198.984,326.853 198.047,326.853 cw(c198.047,326.953) 197.947,326.953 197.947,327.151 cw(c198.047,327.151) 198.047,327.25 198.984,327.25 200.037,327.25 ccw(c200.037,327.35) 200.136,327.35 200.136,327.548 ccw(c200.037,327.548) 200.037,327.647 198.984,327.647 198.047,327.647 cw(c198.047,327.747) 197.947,327.747 197.947,327.945 cw(c198.047,327.945) 198.047,328.044 198.984,328.044 200.01,328.044 ccw(c200.01,328.144) 200.109,328.144 200.109,328.342 ccw(c200.01,328.342) 200.01,328.441 199.015,328.441 cw(c199.015,328.473) 198.984,328.473 198.947,328.509 198.947,332.226 198.477,332.696 198.477,332.709 198.216,332.97 198.207,332.97 198.207,334.741 200.724,337.257 v4(201.656,337.257)
DDR4_CK0: U1.AE30
DDR4_CK1: U1.AF28
DDR4_CK_N: R52.1 U1.AF30 U8.K5 U9.K5 U10.K5 U11.K5 | length 101.2
  L1 w0.1: R52.1@158.737,331.433 ccw(c158.617,331.554) 158.787,331.554 cw(c159.103,331.554) 159.103,331.87 159.828,331.87 cw(c159.828,331.677) v1(160.02,331.677) ; U1.AF30@187.397,317.539 187.87,317.066 v23(187.87,316.954) ; U8.K5@201.257,335.26 v4@201.653,334.864
  L1 w0.116: U9.K5@166.876,335.26 v4(167.279,334.857) ; U11.K5@178.336,335.26 v4(178.74,334.857) ; U10.K5@189.797,335.26 v4(190.2,334.857) ; v4(201.653,334.862) v4@201.653,334.864
  L5 (Sign) w0.1: v23(187.87,316.954) ccw(c188.076,316.954) 188.076,316.748 191.719,316.748 191.771,316.748 ccw(c191.771,316.842) 191.866,316.842 cw(c192.025,316.842) 192.025,317.002 192.06,317.002 cw(c192.06,316.842) 192.22,316.842 ccw(c192.314,316.842) 192.314,316.748 192.397,316.748 ccw(c192.491,316.748) 192.491,316.654 194.024,316.654 ccw(c194.024,319.194) 195.82,317.397 195.957,317.534 ccw(c195.656,317.835) 196.081,317.835 ccw(c195.656,317.835) 195.957,318.135 195.051,319.041 cw(c195.475,319.464) 195.051,319.888 195.132,319.968 cw(c195.555,319.545) 195.979,319.968 198.514,317.433 ccw(c198.815,317.733) 199.115,317.433 199.196,317.513 ccw(c198.895,317.814) 199.32,317.814 ccw(c198.895,317.814) 199.196,318.114 196.66,320.65 cw(c197.084,321.073) 196.66,321.497 196.741,321.577 cw(c197.164,321.154) 197.588,321.577 200.123,319.042 ccw(c200.424,319.343) 200.724,319.042 200.805,319.122 ccw(c200.504,319.423) 200.929,319.423 ccw(c200.504,319.423) 200.805,319.723 199.899,320.629 cw(c200.323,321.053) 199.899,321.476 202.984,324.561 ccw(c201.696,325.849) 203.517,325.849 203.517,326.785 cw(c203.517,326.88) 203.423,326.88 203.423,333.541 ccw(c202.526,333.541) 203.161,334.175 202.938,334.398 ccw(c202.755,334.215) 202.755,334.473 202.042,334.473 cw(c202.042,334.862) v4(201.653,334.862)
  L14 (Sign) w0.1: v1(160.02,331.677) 160.02,331.877 160.42,331.877 160.42,331.89 162.939,331.89 ccw(c162.939,332.325) 163.373,332.325 163.373,335.242 cw(c163.639,335.242) 163.639,335.508 165.001,335.508 ccw(c165.095,335.508) 165.095,335.414 165.705,335.414 cw(c165.705,334.89) 166.076,335.26 166.078,335.259 ccw(c166.599,335.78) 166.599,335.043 167.165,335.043 cw(c167.165,334.928) 167.279,334.928 v4(167.279,334.857) cw(c167.502,334.857) 167.502,335.079 167.918,335.079 ccw(c167.918,336.552) 168.959,335.511 169.026,335.578 cw(c170.687,333.917) 170.687,336.265 173.561,336.265 cw(c173.561,334.243) 174.991,335.673 ; 174.992,335.672 ccw(c176.424,337.105) 176.424,335.079 178.517,335.079 cw(c178.517,334.857) v4(178.74,334.857) cw(c178.966,334.857) 178.966,335.083 179.306,335.083 ccw(c179.306,337.44) 180.972,335.773 181.068,335.869 cw(c181.47,335.466) 181.47,336.035 184.593,336.035 184.594,336.037 184.767,336.037 cw(c184.767,334.213) 186.057,335.503 186.427,335.132 ccw(c187.589,336.294) 187.589,334.651 188.563,334.651 ccw(c188.563,335.494) 189.159,334.898 189.16,334.899 cw(c189.595,334.464) 189.595,335.079 189.978,335.079 cw(c189.978,334.857) v4(190.2,334.857) 190.2,334.92 cw(c190.36,334.92) 190.36,335.08 190.721,335.08 ccw(c190.721,337.822) 192.66,335.883 192.857,336.08 cw(c193.256,335.682) 193.256,336.245 194.894,336.245 cw(c194.894,335.261) 195.59,335.957 195.743,335.804 ccw(c196.487,336.547) 196.487,335.496 199.822,335.496 199.84,335.496 cw(c199.84,335.41) 199.926,335.41 ccw(c200.062,335.41) 200.062,335.274 200.092,335.274 ccw(c200.092,335.41) 200.229,335.41 cw(c200.314,335.41) 200.314,335.496 200.381,335.496 cw(c200.381,335.418) 200.459,335.418 200.459,335.41 ccw(c200.595,335.41) 200.595,335.274 200.626,335.274 ccw(c200.626,335.41) 200.762,335.41 cw(c200.848,335.41) 200.848,335.496 200.914,335.496 200.964,335.496 cw(c200.964,335.36) 201.1,335.36 ccw(c201.236,335.36) 201.236,335.223 201.267,335.223 ccw(c201.267,335.36) 201.403,335.36 cw(c201.539,335.36) 201.539,335.496 201.555,335.496 cw(c201.555,335.178) 201.872,335.178 201.872,335.08 cw(c201.653,335.08) v4(201.653,334.862)
  other v12: -4.475,64.582
DDR4_CK_P: R54.1 U1.AG28 U8.K4 U9.K4 U10.K4 U11.K4 | length 101.5
  L1 w0.1: R54.1@158.737,332.522 cw(c158.617,332.401) 158.787,332.401 ccw(c159.103,332.401) 159.103,332.085 159.828,332.085 ccw(c159.828,332.277) v1(160.02,332.277) ; v23(187.897,316.179) 187.897,316.04 U1.AG28@188.397,315.539 ; U8.K4@202.057,335.26 v4@202.453,334.864
  L1 w0.116: v4(167.272,335.664) U9.K4@167.676,335.26 ; v4(178.733,335.664) U11.K4@179.136,335.26 ; v4(190.193,335.664) U10.K4@190.597,335.26 ; v4(202.453,334.862) v4@202.453,334.864
  L5 (Sign) w0.1: v23(187.897,316.179) cw(c188.103,316.179) 188.103,316.385 192.397,316.385 cw(c192.491,316.385) 192.491,316.48 194.025,316.48 ccw(c194.025,319.192) 195.943,317.274 196.08,317.411 ccw(c195.656,317.835) 196.255,317.835 ccw(c195.656,317.835) 196.08,318.258 195.174,319.164 cw(c195.475,319.464) 195.174,319.765 195.255,319.845 cw(c195.555,319.545) 195.856,319.845 198.391,317.31 ccw(c198.815,317.733) 199.238,317.31 199.319,317.39 ccw(c198.895,317.814) 199.494,317.814 ccw(c198.895,317.814) 199.319,318.237 196.783,320.773 cw(c197.084,321.073) 196.783,321.374 196.864,321.454 cw(c197.164,321.154) 197.465,321.454 200,318.919 ccw(c200.424,319.343) 200.847,318.919 200.928,318.999 ccw(c200.504,319.423) 201.103,319.423 ccw(c200.504,319.423) 200.928,319.847 200.022,320.752 cw(c200.323,321.053) 200.022,321.353 203.108,324.439 ccw(c201.698,325.848) 203.691,325.848 203.691,326.785 ccw(c203.691,326.88) 203.786,326.88 203.786,332.194 203.786,332.266 cw(c203.88,332.266) 203.88,332.361 ccw(c203.88,332.52) 204.04,332.52 204.04,332.556 ccw(c203.88,332.556) 203.88,332.715 cw(c203.88,332.81) 203.786,332.81 203.786,332.892 203.786,332.917 cw(c203.88,332.917) 203.88,333.011 ccw(c203.88,333.171) 204.04,333.171 204.04,333.206 ccw(c203.88,333.206) 203.88,333.365 cw(c203.88,333.46) 203.786,333.46 203.786,333.542 ccw(c202.53,333.542) 203.418,334.43 203.193,334.655 ccw(c202.757,334.22) 202.757,334.835 202.48,334.835 cw(c202.48,334.862) v4(202.453,334.862)
  L14 (Sign) w0.1: v1(160.02,332.277) 160.02,332.077 160.42,332.077 160.42,332.064 162.939,332.064 ccw(c162.939,332.325) 163.199,332.325 163.199,335.242 cw(c163.639,335.242) 163.639,335.682 165.001,335.682 cw(c165.095,335.682) 165.095,335.776 165.708,335.776 cw(c165.708,334.898) 166.33,335.519 166.332,335.517 ccw(c166.601,335.786) 166.601,335.405 167.165,335.405 ccw(c167.165,335.512) 167.272,335.512 v4(167.272,335.664) ccw(c167.495,335.664) 167.495,335.441 167.917,335.441 ccw(c167.917,336.555) 168.704,335.768 168.771,335.835 cw(c170.686,333.92) 170.686,336.628 173.564,336.628 cw(c173.564,334.249) 175.245,335.931 175.247,335.929 ccw(c176.424,337.106) 176.424,335.441 178.51,335.441 ccw(c178.51,335.664) v4(178.733,335.664) ccw(c178.951,335.664) 178.951,335.445 179.302,335.445 ccw(c179.302,337.449) 180.719,336.032 180.813,336.126 cw(c181.468,335.472) 181.468,336.398 184.231,336.398 184.232,336.399 184.917,336.399 cw(c184.917,334.575) 186.207,335.865 186.681,335.39 ccw(c187.592,336.301) 187.592,335.013 188.561,335.013 ccw(c188.561,335.497) 188.904,335.155 188.905,335.156 cw(c189.594,334.467) 189.594,335.441 189.971,335.441 ccw(c189.971,335.664) v4(190.193,335.664) 190.193,335.609 ccw(c190.36,335.609) 190.36,335.442 190.655,335.442 ccw(c190.655,337.982) 192.451,336.186 192.602,336.337 cw(c193.254,335.685) 193.254,336.607 194.896,336.607 cw(c194.896,335.266) 195.845,336.214 195.999,336.06 ccw(c196.487,336.549) 196.487,335.858 200.952,335.858 201.014,335.858 ccw(c201.014,335.944) 201.1,335.944 cw(c201.236,335.944) 201.236,336.08 201.267,336.08 cw(c201.267,335.944) 201.403,335.944 ccw(c201.489,335.944) 201.489,335.858 201.555,335.858 cw(c201.555,335.178) 202.235,335.178 202.235,335.08 ; 202.235,335.028 202.235,335.08 ; v4(202.453,334.862) cw(c202.453,335.08) 202.235,335.08
DDR4_CKE0: R38.1 U1.AC30 U8.K2 U9.K2 U10.K2 U11.K2 | length 110.3
  L1 w0.116: U9.K2@171.676,335.26 v4(172.079,334.857) ; U11.K2@183.136,335.26 v4(183.54,334.857) ; U1.AC30@184.397,317.539 v6(184.884,317.052) ; U10.K2@194.597,335.26 v4(195,334.857) ; U8.K2@206.057,335.26 v15(206.461,334.857)
  L1 w0.155: v1(162.769,343.555) R38.1@162.769,344.8
  L5 (Sign) w0.092: 167.571,341.085 168.41,340.246 168.41,336.122 170.071,334.46 171.683,334.46 v4(172.079,334.857) 172.333,334.857 172.675,334.515 173.142,334.515 173.997,333.66 174.131,333.66 cw(c174.131,333.571) 174.221,333.571 174.221,333.511 ccw(c174.31,333.511) 174.31,333.422 174.579,333.422 ccw(c174.579,333.511) 174.668,333.511 174.668,333.571 cw(c174.758,333.571) 174.758,333.66 175.73,333.66 181.536,333.66 182.336,334.46 182.629,334.46 183.025,334.857 v4(183.54,334.857) 184.385,334.012 184.654,334.012 185.805,332.86 191.573,332.86 193.173,334.46 193.955,334.46 194.352,334.857 v4(195,334.857) 195.07,334.857 195.249,334.677 195.971,334.677 196.613,334.035 196.613,333.411 196.954,333.07 198.216,333.07 198.444,333.07 cw(c198.444,332.981) 198.534,332.981 198.534,332.734 ccw(c198.623,332.734) 198.623,332.644 198.892,332.644 ccw(c198.892,332.734) 198.982,332.734 198.982,333.07 198.982,333.407 cw(c199.071,333.407) 199.071,333.496 199.34,333.496 cw(c199.34,333.407) 199.43,333.407 199.43,333.07 199.43,332.734 ccw(c199.519,332.734) 199.519,332.644 199.788,332.644 ccw(c199.788,332.734) 199.877,332.734 199.877,332.981 cw(c199.967,332.981) 199.967,333.07 200.101,333.07 200.416,333.385 200.416,334.158 201.508,335.25 203.375,335.25 204.146,334.48 206.084,334.48 v15(206.461,334.857)
  L5 (Sign) w0.151: v1(162.769,343.555) 162.769,342.831 164.224,341.376 167.28,341.376 167.571,341.085
  L3 (Sign) w0.092: v6(184.884,317.052) 184.884,316.531 186.231,315.185 186.231,314.919 185.857,314.546 185.678,314.546 185.504,314.372 185.504,312.908 185.822,312.59 186.168,312.59 188.759,309.999 192.411,309.999 192.45,310.038 192.458,310.038 205.797,323.376 205.797,324.587 207.05,325.839 207.05,329.514 207.05,329.613 ccw(c206.95,329.613) 206.95,329.713 206.939,329.713 cw(c206.939,329.812) 206.84,329.812 206.84,330.01 cw(c206.939,330.01) 206.939,330.11 207.05,330.11 207.306,330.11 ccw(c207.306,330.209) 207.405,330.209 207.405,330.407 ccw(c207.306,330.407) 207.306,330.507 207.05,330.507 206.358,330.507 cw(c206.358,330.606) 206.259,330.606 206.259,330.804 cw(c206.358,330.804) 206.358,330.904 207.05,330.904 207.166,330.904 ccw(c207.166,331.003) 207.265,331.003 207.265,331.201 ccw(c207.166,331.201) 207.166,331.301 207.05,331.301 206.938,331.301 cw(c206.938,331.4) 206.839,331.4 206.839,331.598 cw(c206.938,331.598) 206.938,331.698 206.95,331.698 ccw(c206.95,331.797) 207.05,331.797 207.05,333.438 207.05,333.539 206.461,334.128 v15(206.461,334.857)
DDR4_CKE1: U1.AB28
